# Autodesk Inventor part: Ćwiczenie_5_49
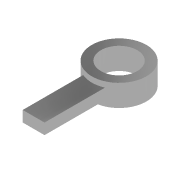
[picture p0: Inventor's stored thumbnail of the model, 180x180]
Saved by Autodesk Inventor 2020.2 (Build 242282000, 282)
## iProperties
Created: 2005-07
Part Number: Ćwiczenie_5_49
Document SubType Name: Modeling
Designer: F.Stasiak
Manufacturer: Standard
Standards Organization: Custom
Density: 1 g/cm^3
Material: Ogólny
Appearance: Chrom — polerowany
Manager: www.cadconsulting.pl
Company: Fabian Stasiak CAD Consulting
Author: F.Stasiak
Subject: Zbiór ćwiczeń. Autodesk Inventor 2020. Kurs podstawowy
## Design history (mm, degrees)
sketch "Szkic1"
  geometry: C1 r 10 at (0, 0); C2 r 15 at (0, 0)
  constraints: 2 centre point, 1 coincident
  dimensions: "d0" = 20 diameter of C1; "d1" = 30 diameter of C2
extrude "Wyciągnięcie proste1" new body sketch "Szkic1" stored distance "d2" = 12; taper "d3" = 0 deg
sketch "Szkic2"
  geometry: L1 (-47, 6)-(-12, 6); L2 (-12, 6)-(-12, -6); L3 (-12, -6)-(-47, -6); L4 (-47, -6)-(-47, 6); 1 further point
  constraints: 8 end point, 2 parallel, 1 horizontal, 1 perpendicular
  dimensions: "d5" = 12 distance from line of point (0, 0) L2; "d6" = 12 distance of L3.end L1.start; "d7" = 6 distance from line of point (0, 0) L3 (= 0.5 x d6); "d18" = 35 distance of L2.end L3.end
extrude "Wyciągnięcie proste2" join sketch "Szkic2" stored distance "d8" = 6; taper "d9" = 0 deg
node "Bryła1"
node "Korpusy bryłowe"
node "Korpusy powierzchniowe"
